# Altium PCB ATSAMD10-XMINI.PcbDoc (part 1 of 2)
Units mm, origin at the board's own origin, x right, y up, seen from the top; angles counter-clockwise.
Board outline 60 x 75 mm, 4 copper layers (Top Layer, GND, Power Plane, Bottom Layer), stack 1.578 mm thick; 62 components, 78 nets, 549 pads, 117 vias.
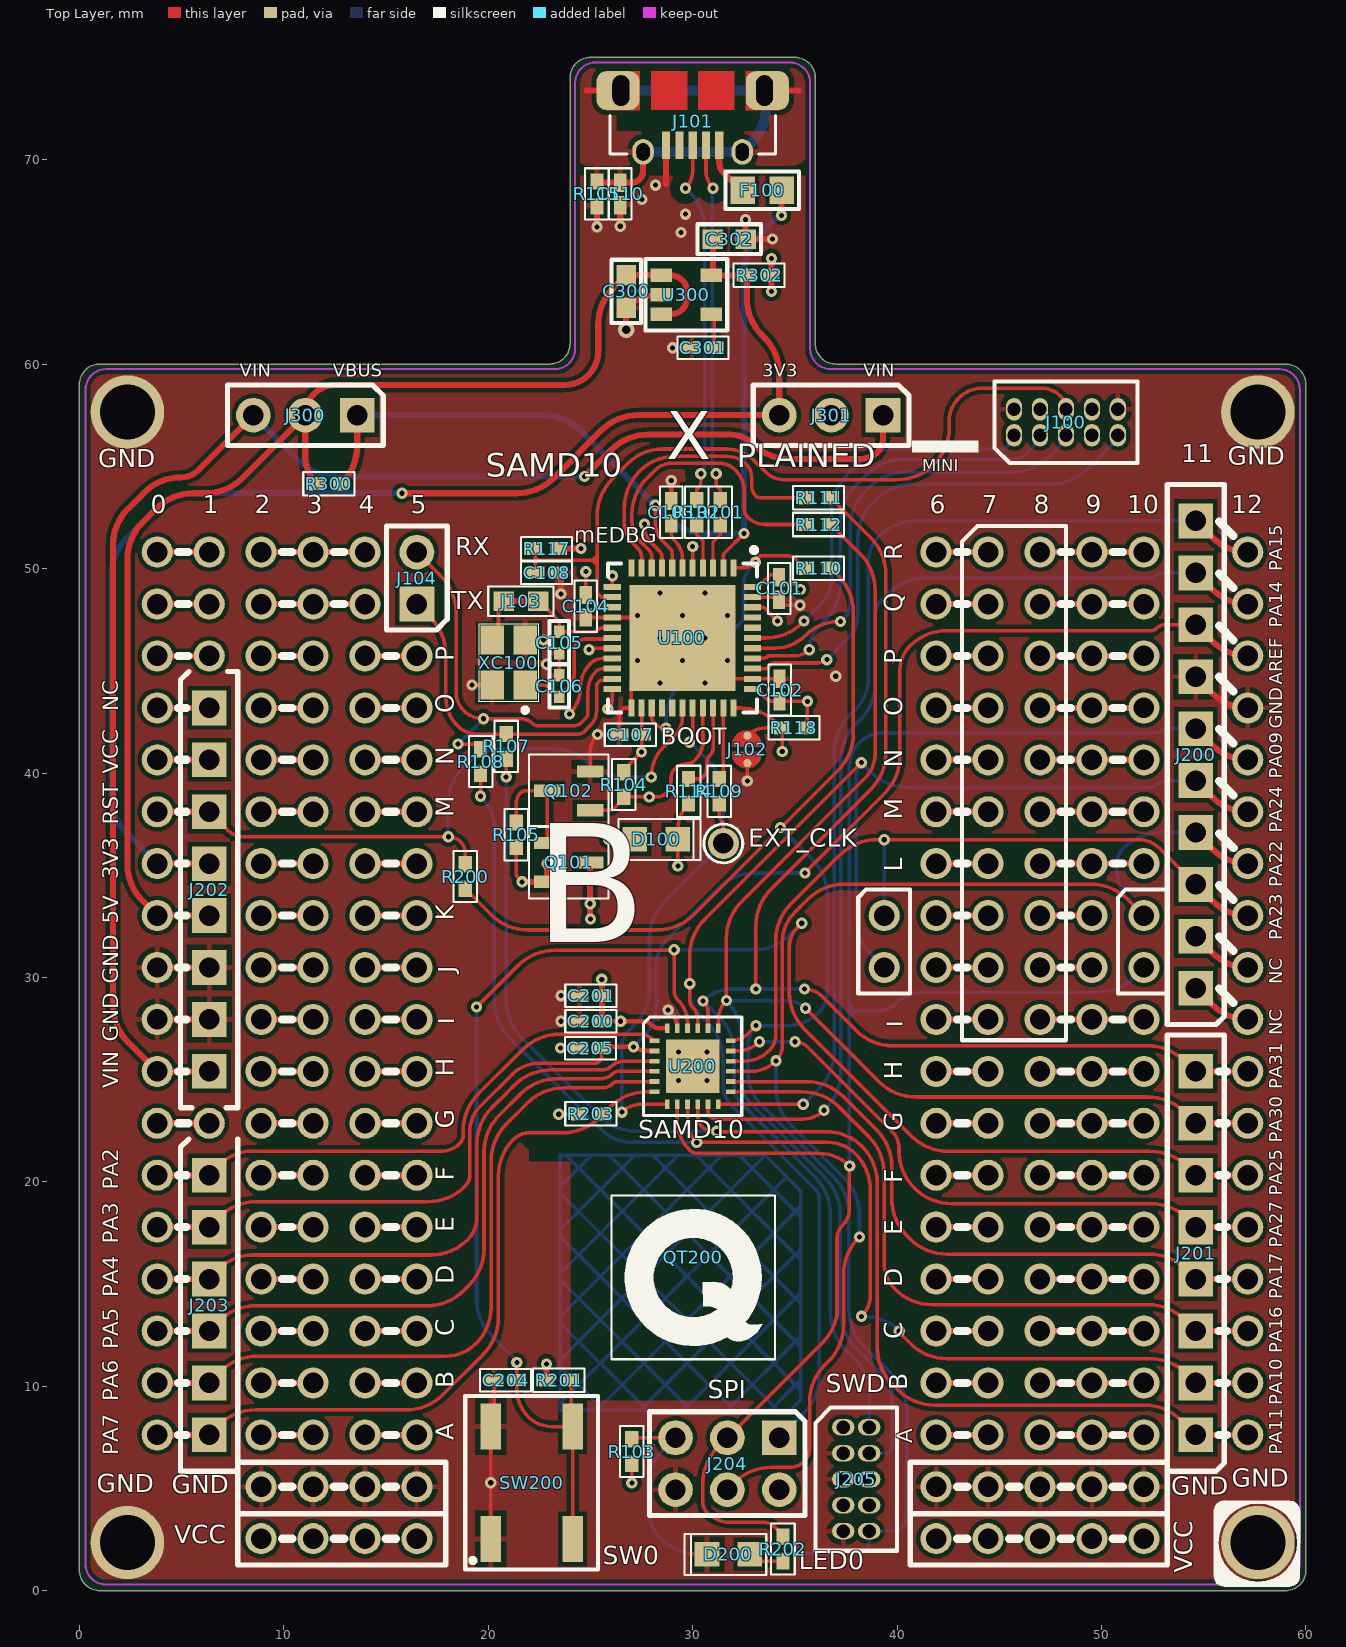
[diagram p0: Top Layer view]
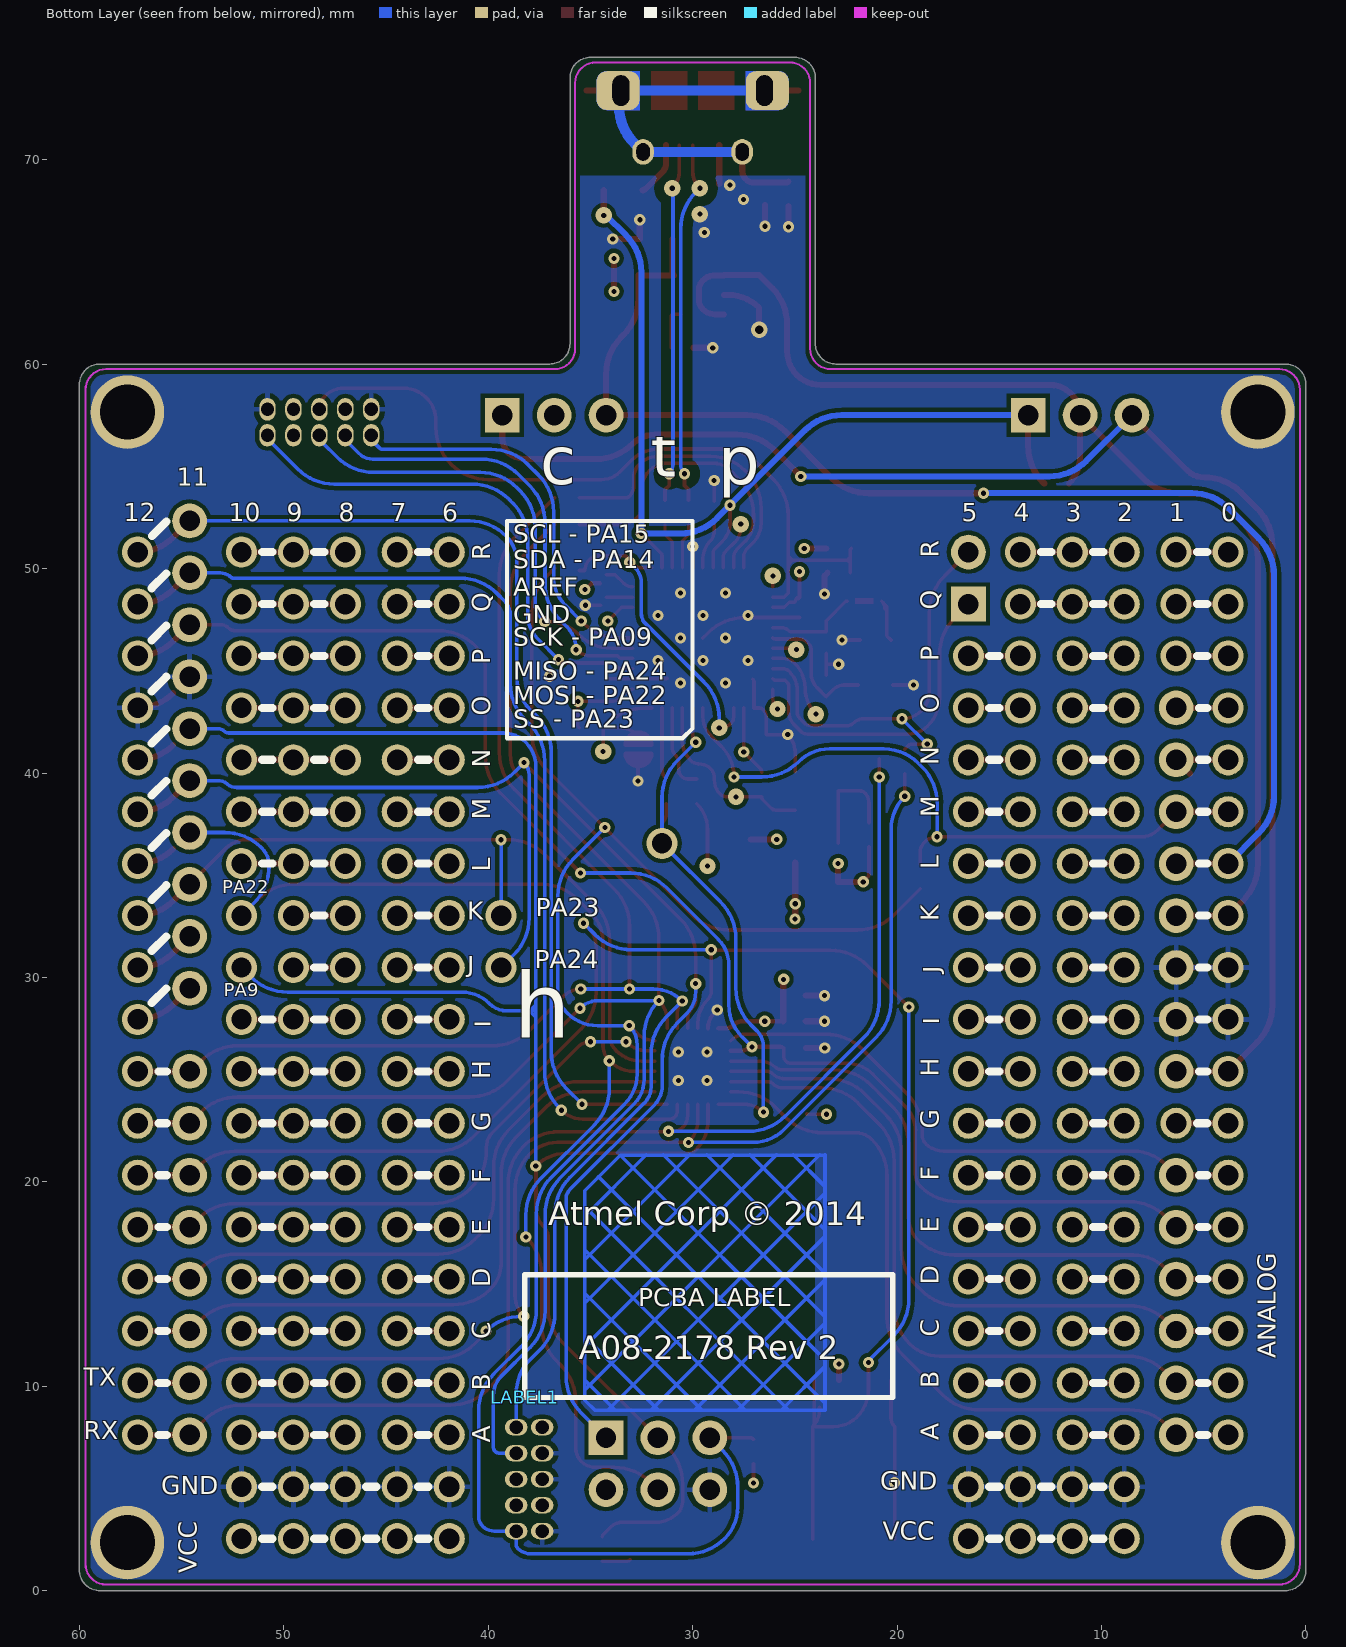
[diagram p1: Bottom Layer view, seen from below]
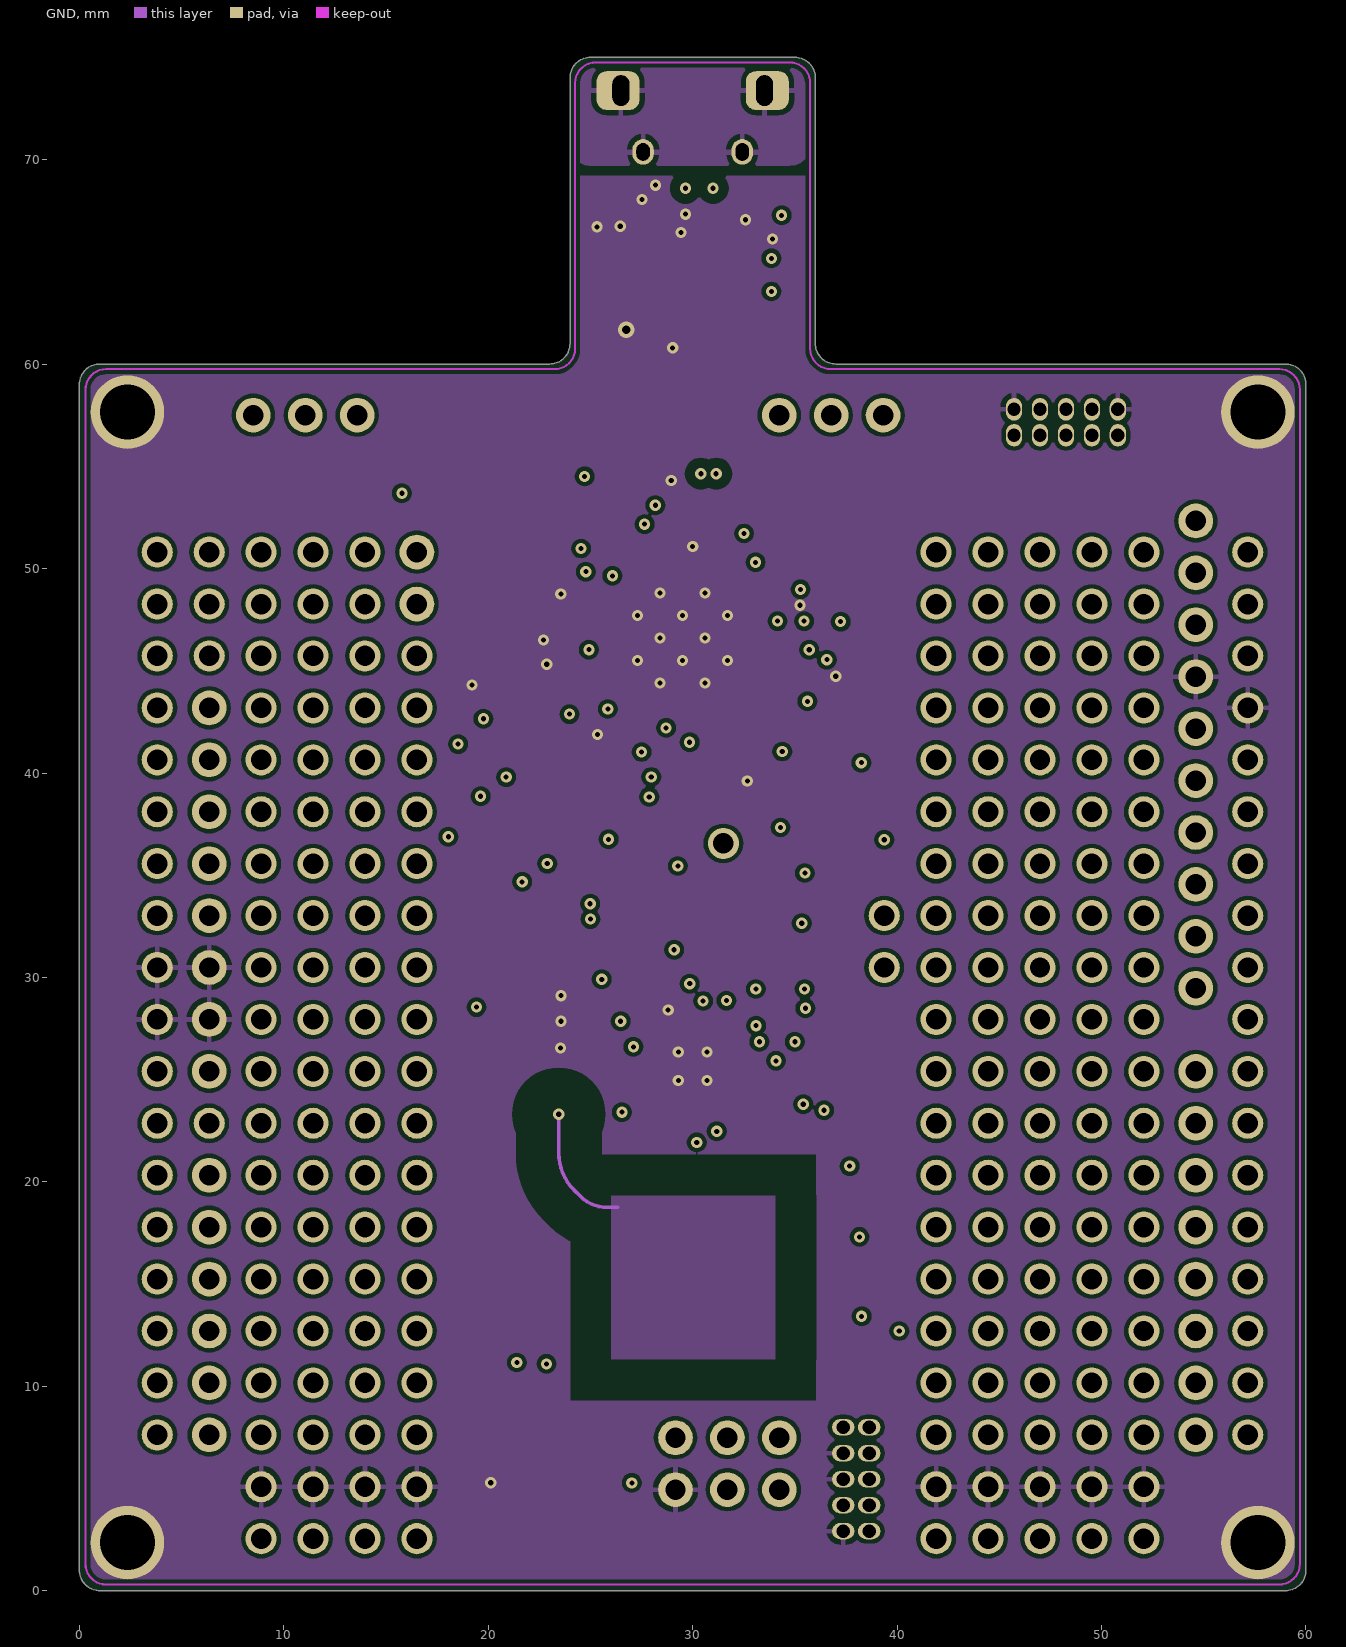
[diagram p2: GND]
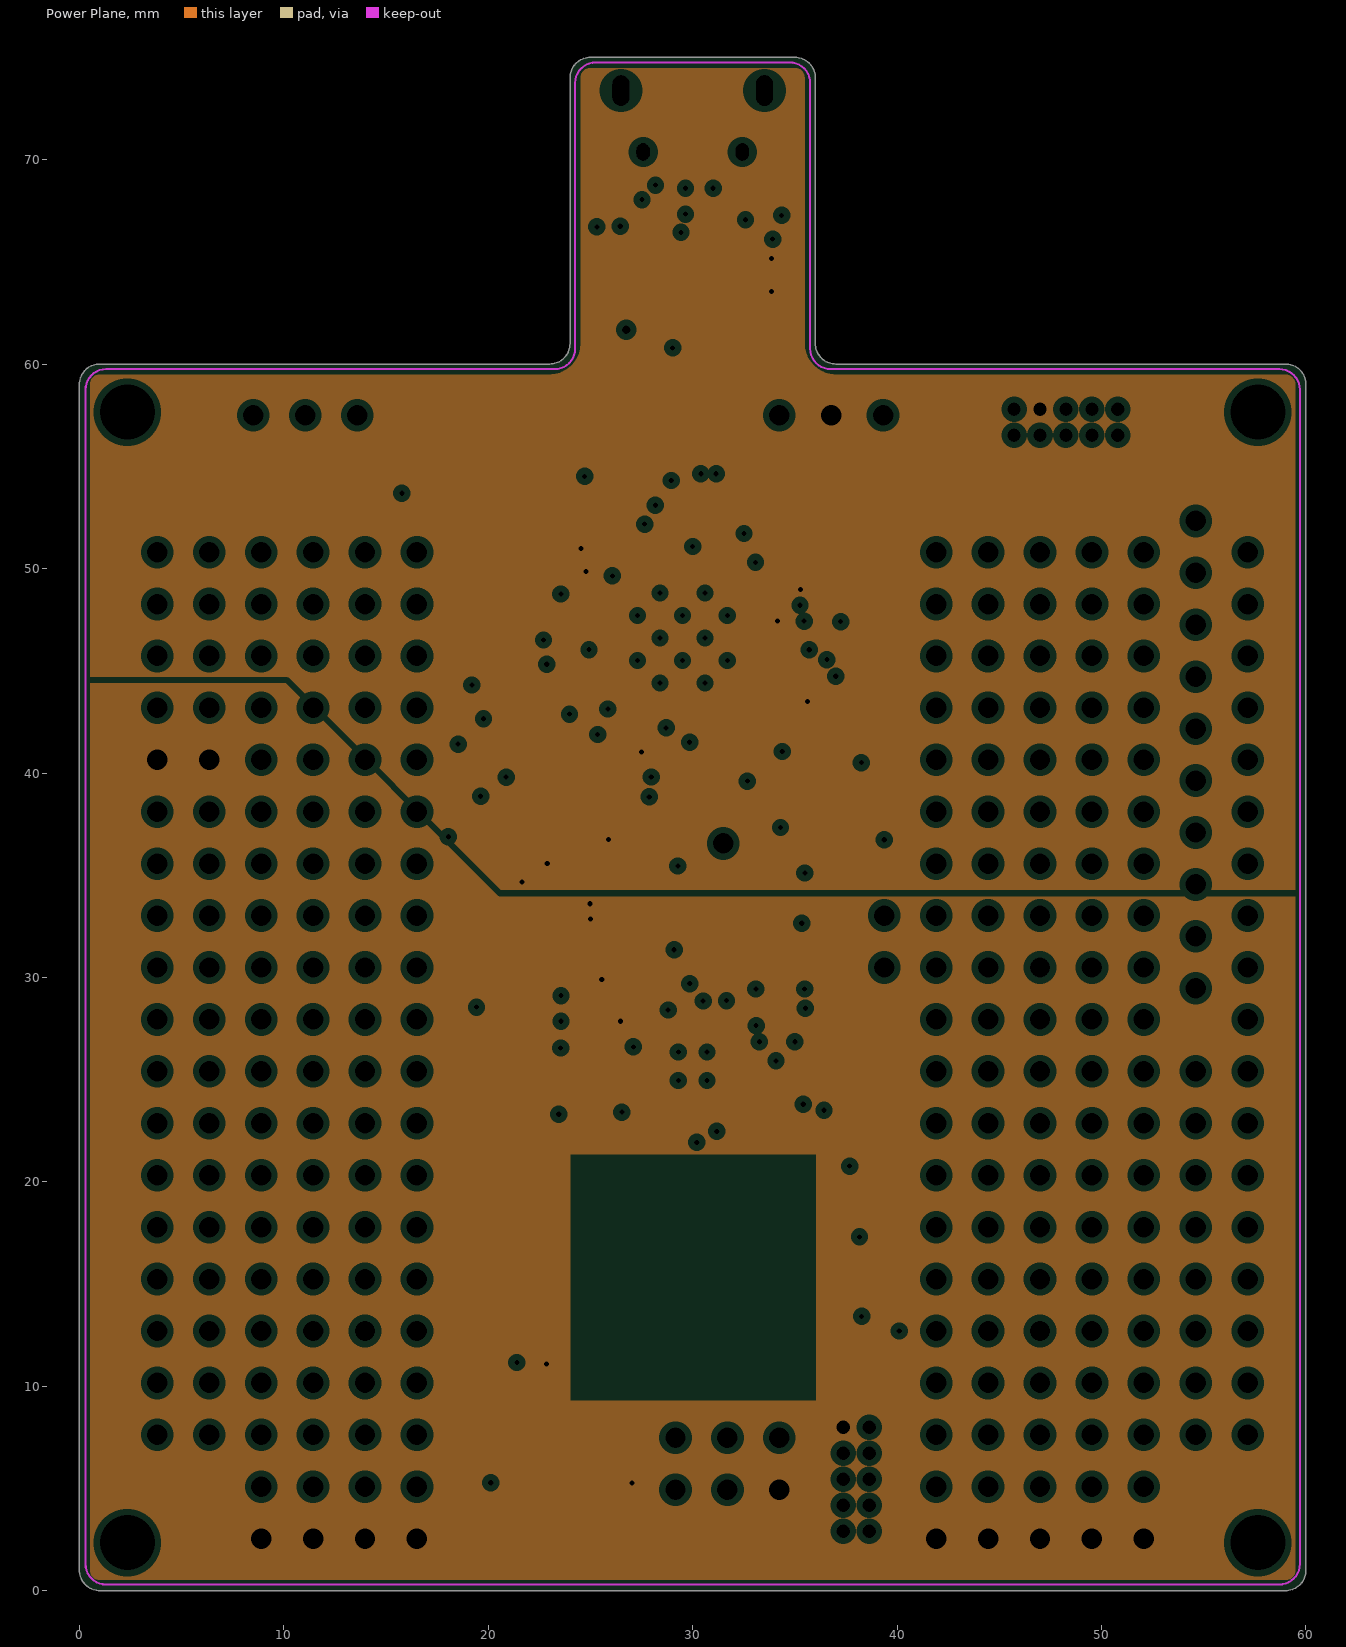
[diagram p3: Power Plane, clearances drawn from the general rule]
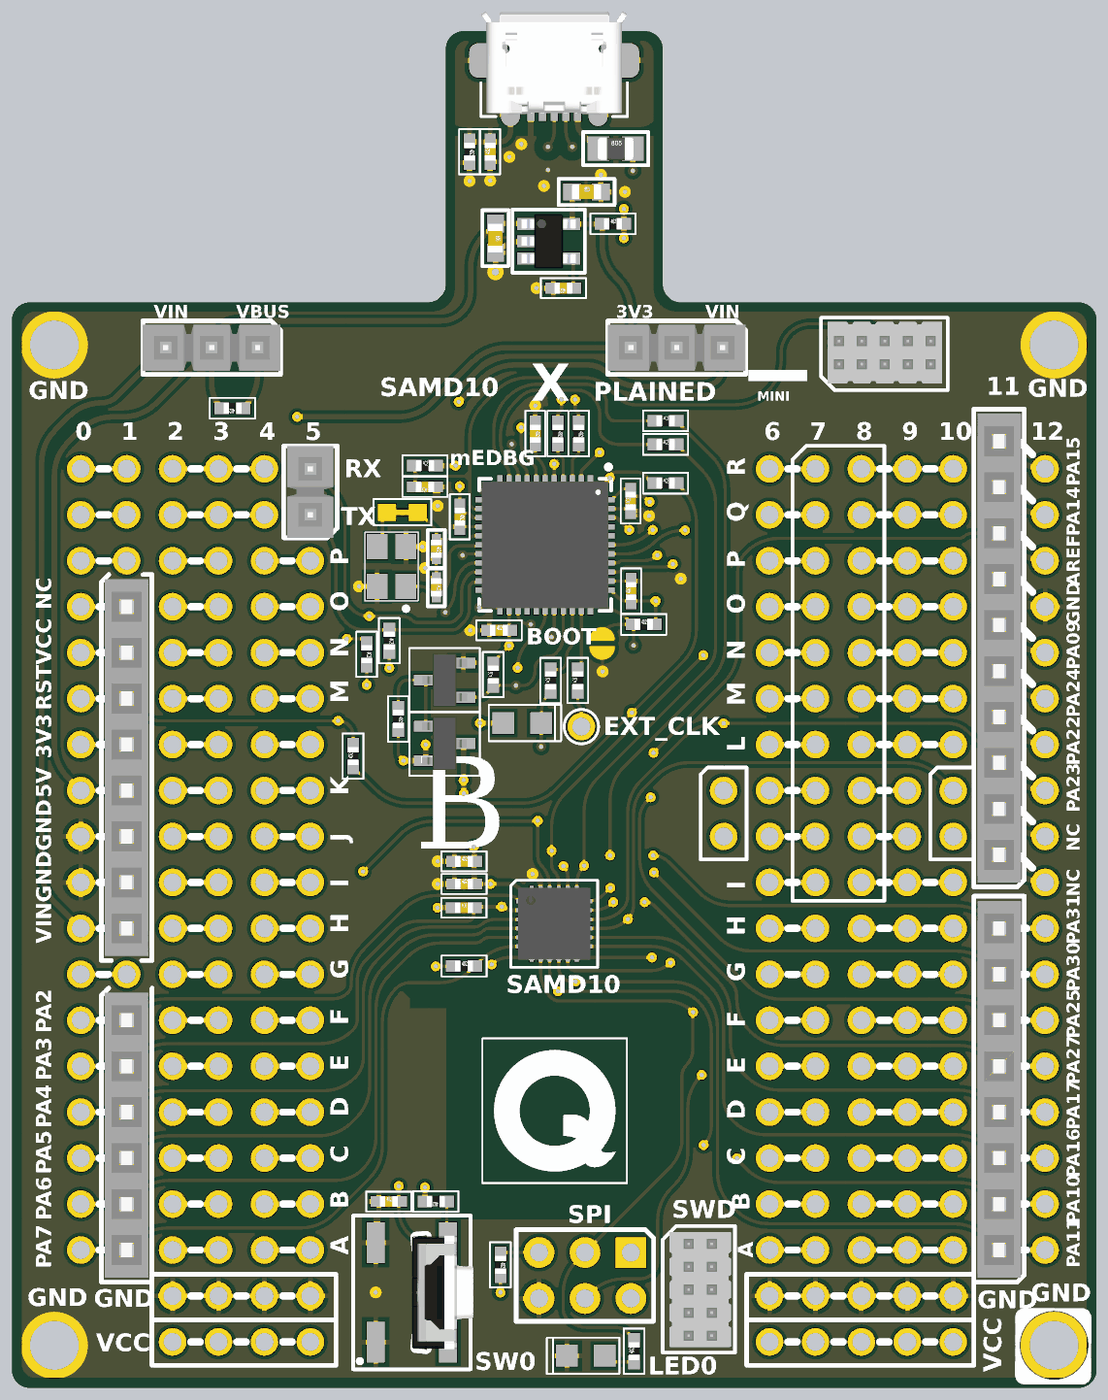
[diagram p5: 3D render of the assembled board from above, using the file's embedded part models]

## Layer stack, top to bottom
Top Solder: solder mask 0.0102, Solder Resist, Dk 3.5
Top Layer: signal copper 0.0356
Dielectric 1: prepreg 0.118, Dk 4.2
GND: signal copper 0.0356
Dielectric 2: core 1.2, Dk 4.2
Power Plane: plane copper 0.0356, net (Multiple Nets)
Dielectric 3: prepreg 0.118, Dk 4.2
Bottom Layer: signal copper 0.0356
Bottom Solder: solder mask 0.0102, Solder Resist, Dk 3.5

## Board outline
0,1.009 0,59.009 cw(c1,59.009) 1,60.009 23,60.009 ccw(c23,61.009) 24,61.009 24,74.009 cw(c25,74.009) 25,75.009 35,75.009 cw(c35,74.009) 36,74.009 36,61.009 ccw(c37,61.009) 37,60.009 59,60.009 cw(c59,59.009) 60,59.009 60,1.009 cw(c59,1.009) 59,0.009 1,0.009 cw(c1,1.009)

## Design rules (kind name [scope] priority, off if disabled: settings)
AcuteAngle [All] p1: minimum=7.50000000000000E+0001 checktracksonly=FALSE
AssemblyTestPointUsage [All] p1: allowmultiple=TRUE
AssemblyTestpoint [All] p1: testpointundercomponent=TRUE minsize=0.55 maxsize=2 preferedsize=0.8 minholesize=0 maxholesize=1 preferedholesize=0.25 testpointgrid=0.025 usegrid=FALSE gridtolerance=0 allowsidebottom=TRUE minspacing=1.27 compbodyclearance=0.127
Clearance Clearance_1 [InNet('NetQT200_1') vs (InNamedPolygon('L2-GND') OR InNamedPolygon('Top-GND'))] p1: gap=2 ignorepadtopadclearanceinfootprint=FALSE except(0: Arc-Hole Track-Hole SMDPad-Hole THPad-Hole Via-Hole Fill-Hole Poly-Hole Region-Hole Text-Hole)
Clearance Clearance_Poly [InPoly vs InNet('USBD_P') OR InNet('USBD_N')] p2: gap=0.5 ignorepadtopadclearanceinfootprint=FALSE except(0: Arc-Hole Track-Hole SMDPad-Hole THPad-Hole Via-Hole Fill-Hole Poly-Hole Region-Hole Text-Hole)
Clearance Clearance_Poly_1 [InPoly] p3: gap=0.2 ignorepadtopadclearanceinfootprint=FALSE except(0: Arc-Hole Track-Hole SMDPad-Hole THPad-Hole Via-Hole Fill-Hole Poly-Hole Region-Hole Text-Hole)
Clearance [All] p4: gap=0.15 ignorepadtopadclearanceinfootprint=FALSE except(0: Arc-Hole Track-Hole SMDPad-Hole THPad-Hole Via-Hole Fill-Hole Poly-Hole Region-Hole Text-Hole)
DiffPairsRouting [All] p1: maxlimit=0.3 minlimit=0.15 mostfreqgap=0.2 toplayer_minwidth=0.15 toplayer_maxwidth=0.18 toplayer_prefwidth=0.15 midlayer1_minwidth=0.15 midlayer1_maxwidth=0.18 midlayer1_prefwidth=0.15 bottomlayer_minwidth=0.15 bottomlayer_maxwidth=0.18 bottomlayer_prefwidth=0.15 maxuncoupledlength=20
FabricationTestPointUsage TestPointUsage [All] p1: valid=0 allowmultiple=TRUE
FabricationTestpoint Testpoint [All] p1: side=2 testpointundercomponent=TRUE minsize=0.55 maxsize=2 preferedsize=0.8 minholesize=0 maxholesize=1 preferedholesize=0.25 testpointgrid=0 allowsidebottom=TRUE usegrid=FALSE gridtolerance=0 minspacing=1.27 compbodyclearance=0.127
HoleSize [All] p1: absolutevalues=TRUE maxlimit=10 minlimit=0.25 maxpercent=80.000 minpercent=20.000
HoleToHoleClearance [All] p1: gap=0.45 allowstackedmicrovias=TRUE
MinimumAnnularRing MinimumAnnularRing_JTAG [(InComponent('J100') AND InComponent('J205'))] p1: minimumring=0.05
MinimumAnnularRing [All] p2: minimumring=0.15
MinimumSolderMaskSliver [All] p1: minsoldermaskwidth=0.05
PlaneClearance [All] p1: clearance=0.3
PlaneConnect PlaneConnect_VIA [IsVia OR HasPad('Free-666')] p1: planeconnectstyle=Direct reliefexpansion=0.508 reliefentries=4 reliefconductorwidth=0.254 reliefairgap=0.254
PlaneConnect [All] p2: planeconnectstyle=Relief reliefexpansion=0.508 reliefentries=4 reliefconductorwidth=0.254 reliefairgap=0.254
PolygonConnect PolygonConnect_VIA [IsVia OR HasPad('Free-666')] p1: connectstyle=Direct reliefconductorwidth=0.254 reliefentries=4 polygonreliefangle="90 Angle" airgapwidth=0.254
PolygonConnect [All] p2: connectstyle=Relief reliefconductorwidth=0.254 reliefentries=4 polygonreliefangle="90 Angle" airgapwidth=0.254
RoutingVias [All] p1: holewidth=0.25 width=0.55 viastyle="Through Hole" minholewidth=0.25 minwidth=0.55 maxholewidth=0.5 maxwidth=1
SMDNeckDown [All] p1: percent=90.000
SilkToSilkClearance SilkToSilkClearance_Text [IsText] p1: silktosilkclearance=0
SilkToSilkClearance [All] p2: silktosilkclearance=0.1
SilkToSolderMaskClearance SilkscreenOverComponentPads [IsPad] p1: minsilkscreentomaskgap=0.05 clearancetoexposedcopper=TRUE
SolderMaskExpansion SolderMaskTenting [IsVia AND NOT (IsFabTestpoint OR IsAssyTestpoint)] p1: expansion=-1
SolderMaskExpansion [All] p2: expansion=0.05
ViasUnderSMD [All] p1: allowed=FALSE
Width [All] p1: maxlimit=10 minlimit=0.175 preferedwidth=0.175
18 further rules are at their usual default settings.

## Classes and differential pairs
component class ATSAMD10-XMINI_TopLevel: FW1 LABEL1 PCB1 PCBADOC1 TEST2 TESTDOC1
component class "Target device": C200 C201 C204 C205 D200 J200 J201 J202 J203 J204 J205 QT200 R200 R201 R202 R203 R204 SW200 U200
component class Programmer/Debug: C101 C102 C103 C104 C105 C106 C107 C108 C110 C300 C301 C302 D100 F100 J100 J101 J102 J103 J104 J300 J301 Q101 Q102 R101 R102 R103 R104 R105 R107 R108 R109 R110 R111 R112 R114 R115 R117 R118 R300 R302 U100 U300 XC100
differential pair D: +D_P -D_N
differential pair USBD: +USBD_P -USBD_N

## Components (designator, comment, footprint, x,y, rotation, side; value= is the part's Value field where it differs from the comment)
C101 "" AP1-00001 34.225,49.034 r90 top value=100n
C102 "" AP1-00001 34.25,44.059 r90 top value=100n
C103 "" AP1-00001 28.95,52.759 r270 top value=1u
C104 "" AP1-00001 24.775,48.159 r270 top value=100n
C105 "" AP1-00038 23.475,45.859 r180 top value=12pF
C106 "" AP1-00038 23.475,43.734 r180 top value=12pF
C107 "" AP1-00001 26.95,41.884 r0 top value=100n
C108 "" AP1-00001 22.85,49.809 r180 top value=100n
C110 "" AP1-00001 26.458,68.335 r90 top value=4.7n
C200 "" AP1-00001 25.016,27.861 r0 top value=100n
C201 "" AP1-00001 25.016,29.111 r0 top value=100n
C204 "" AP1-00001 20.85,10.309 r0 top value=100n
C205 "" AP1-00001 25,26.55 r0 top value=100n
C300 "Farnell no.: 1833806" AP1-00002 26.747,63.561 r270 top value=4.7uF
C301 "" AP1-00001 30.503,60.802 r180 top value=10n
C302 "Farnell no.: 1833806" AP1-00002 31.786,66.12 r0 top value=4.7uF
D100 "" AP4-00013 28.225,36.759 r180 top value=EL17-21SYGC
D200 "" AP4-00013 31.75,1.784 r0 top value=EL17-21UYC/A3
F100 "Farnell no: 1861197" AP2-00002 33.4,68.509 r0 top value=MC36213
J100 "" AP8-00257 48.26,57.159 r0 top locked value="PIN HEADER 2x5"
J101 "2,000 pieces per reel" AP8-00851 30,73.384 r180 top locked value=ZX62D-B-5PA8
J102 "" AP9-00034 32.675,41.159 r90 top net-tie value=SMD-STRAP_OPEN
J103 "" AP9-00044 21.6,48.409 r0 top net-tie value=SMD-STRAP_0603_CLOSED
J104 "" AP8-00733 16.51,49.539 r90 top locked value=HMTSW-102-23-F-S-237
J200 "" AP8-00822 54.61,40.903 r90 top locked value=SSQ-110-21-F-S
J201 "" AP8-00823 54.61,16.519 r90 top locked value=SSQ-108-21-F-S
J202 "" AP8-00823 6.35,34.299 r270 top locked value=SSQ-108-21-F-S
J203 "" AP8-00824 6.35,13.979 r270 top locked value=SSQ-106-21-F-S
J204 "" AP8-00182 31.7,6.219 r180 top locked value=MTSW-103-08-L-D-276
J205 "" AP8-00257 38,5.459 r270 top value="PIN HEADER 2x5"
J300 "" AP8-00745 11.05,57.509 r180 top value=HMTSW-103-23-F-S-237
J301 "" AP8-00745 36.775,57.509 r180 top value=HMTSW-103-23-F-S-237
LABEL1 "" AP8-00317 38.21,9.459 r180 bottom value="Label PCBA"
Q101 "" AP5-00002 23.935,35.629 r0 top value=IRLML6402
Q102 "" AP5-00002 23.935,39.129 r180 top value=2N7002,215
QT200 "QTouch Button" ? 30.028,16.325 r0 top
R101 "" AP2-00000 31.35,52.759 r270 top value=22R
R102 "" AP2-00000 30.2,52.759 r270 top value=22R
R103 "" AP2-00000 27.025,6.809 r270 top value=3.3k
R104 "" AP2-00000 26.625,39.434 r90 top value=100k
R105 "" AP2-00000 21.375,36.984 r270 top value=100k
R107 "" AP2-00000 20.875,41.309 r270 top value=1k
R108 "" AP2-00000 19.625,40.559 r270 top value=1k
R109 "" AP2-00000 31.3,39.109 r90 top value=330R
R110 "" AP2-00000 36.158,50.016 r0 top value=0R
R111 "" AP2-00000 36.158,53.466 r0 top value=330R
R112 "" AP2-00000 36.158,52.159 r0 top value=330R
R114 "" AP2-00000 29.8,39.109 r90 top value=680R
R115 "" AP2-00000 25.315,68.335 r270 top value=1M
R117 "" AP2-00000 22.85,50.984 r0 top value=100k
R118 "" AP2-00000 34.95,42.209 r0 top value=100k
R200 "" AP2-00000 18.875,34.934 r90 top value=0R
R201 "" AP2-00000 23.45,10.309 r180 top value=100k
R202 "" AP2-00000 34.417,2.041 r90 top value=1k
R203 "" AP2-00000 25.016,23.325 r0 top value=100k
R300 "" AP2-00000 12.2,54.159 r180 top value=0R
R302 "" AP2-00000 33.251,64.357 r0 top value=0R
SW200 "" AP8-00137 22.125,5.284 r90 top value=SKRAAKE010
U100 "" AP6-00375 29.5,46.609 r270 top value=ATmega32U4-MUR
U200 "" AP6-00371 30,25.659 r0 top value=ATSAMD10D14A-MUT
U300 "" AP6-00087 29.693,63.392 r0 top value=LP2985-33DBV
XC100 "" AP7-00061 21,45.409 r90 top value=16.0MHz

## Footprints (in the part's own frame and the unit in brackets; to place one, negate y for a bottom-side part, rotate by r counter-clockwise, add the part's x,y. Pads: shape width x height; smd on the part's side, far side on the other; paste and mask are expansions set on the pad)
AP1-00001 [mm] "Standard 0402 SMD capacitor footprint"
  rect 0.9x0.6 smd: 1(-0.55,0) 2(0.55,0)
  silkscreen extent -1.25,-0.55 1.25,0.55, body extent -0.5,-0.3 0.5,0.3, height 0.2
AP1-00002 [mm]
  rect 1x0.95 smd: 1(-0.8,0) 2(0.8,0)
  silkscreen extent -1.55,-0.72 1.55,0.72, body extent -0.8,-0.4 0.8,0.4, height 0.3
AP1-00038 [mm] "Generic pad 0402, spacing 0.45mm"
  rect 0.5x0.6 smd: 1(0,0) 2(0,-1.05)
  silkscreen extent -0.48,-1.58 0.48,0.53, body extent -0.3,-1.02 0.3,-0.03, height 0.2
AP2-00000 [mm] "Standard 0402 SMD resistor footprint"
  rect 0.8x0.65 smd: 1(-0.6,0) 2(0.6,0)
  silkscreen extent -1.25,-0.58 1.25,0.58, body extent -0.5,-0.3 0.5,0.3, height 0.2
AP2-00002 [mm]
  rect 1.2x1.35 smd: 1(-0.95,0) 2(0.95,0)
  silkscreen extent -1.8,-0.92 1.8,0.92, body extent -1,-0.62 1,0.63, height 0.78
AP4-00013 [mm] "0805 diode footprint"
  rect 1.2x1.2 smd: 1(-1.05,0) 2(1.05,0)
  silkscreen extent -2.16,-1 1.85,1, body extent -1,-0.63 1,0.63, height 1.1
AP5-00002 [mm] "SOT-23 Package"
  rect 1.3x0.6 smd: 1(-1.05,0.95) 2(-1.05,-0.95) 3(1.05,0)
  silkscreen extent -1.95,-1.78 1.95,1.78, body extent -1.25,-1.46 1.23,1.46, height 1
AP6-00087 [mm]
  rect 1.05x0.65 smd: 1(-1.225,0.953) 2(-1.225,0) 3(-1.225,-0.953) 4(1.225,-0.953) 5(1.225,0.953)
  silkscreen extent -2,-1.75 2,1.75, body extent -1.5,-1.5 1.5,1.5, height 1.3
AP6-00371 [mm] "QFN24, 4x4mm, 0.4 pitch"
  round 0.6 on Top Paste: 0(-0.65,-0.65) 0(-0.65,0.65) 0(0,0) 0(0.65,-0.65) 0(0.65,0.65)
  rect 0.48x0.23 smd: 1(-1.86,1.25) 2(-1.86,0.75) 3(-1.86,0.25) 4(-1.86,-0.25) 5(-1.86,-0.75) 6(-1.86,-1.25) 13(1.86,-1.25) 14(1.86,-0.75) 15(1.86,-0.25) 16(1.86,0.25) 17(1.86,0.75) 18(1.86,1.25)
  rect 0.23x0.48 smd: 7(-1.25,-1.86) 8(-0.75,-1.86) 9(-0.25,-1.86) 10(0.25,-1.86) 11(0.75,-1.86) 12(1.25,-1.86) 19(1.25,1.86) 20(0.75,1.86) 21(0.25,1.86) 22(-0.25,1.86) 23(-0.75,1.86) 24(-1.25,1.86)
  rect 2.6x2.6 smd paste-2: 25(0,0)
  silkscreen extent -2.4,-2.4 2.4,2.4, body extent -2,-2 2,2, height 1
AP6-00375 [mm] "QFN, 44-Leads, Body 7,00x7,00mm, Pitch 0,50mm, Thermal Pad 5,20x5,20mm, IPC Medium Density"
  rect 0.85x0.3 smd: 1(-3.425,2.5) 2(-3.425,2) 3(-3.425,1.5) 4(-3.425,1) 5(-3.425,0.5) 6(-3.425,0) 7(-3.425,-0.5) 8(-3.425,-1) 9(-3.425,-1.5) 10(-3.425,-2) 11(-3.425,-2.5) 23(3.425,-2.5) 24(3.425,-2) 25(3.425,-1.5) 26(3.425,-1) 27(3.425,-0.5) 28(3.425,0) 29(3.425,0.5) 30(3.425,1) 31(3.425,1.5) 32(3.425,2) 33(3.425,2.5)
  rect 0.3x0.85 smd: 12(-2.5,-3.425) 13(-2,-3.425) 14(-1.5,-3.425) 15(-1,-3.425) 16(-0.5,-3.425) 17(0,-3.425) 18(0.5,-3.425) 19(1,-3.425) 20(1.5,-3.425) 21(2,-3.425) 22(2.5,-3.425) 34(2.5,3.425) 35(2,3.425) 36(1.5,3.425) 37(1,3.425) 38(0.5,3.425) 39(0,3.425) 40(-0.5,3.425) 41(-1,3.425) 42(-1.5,3.425) 43(-2,3.425) 44(-2.5,3.425)
  rect 5.2x5.2 smd: 45(0,0)
  silkscreen extent -4.42,-3.65 3.65,3.65, body extent -3.5,-3.5 3.5,3.5, height 0.89
AP7-00061 [mm] "TSX-3225"
  rect 1.4x1.15 smd: 1(-1.1,-0.8) 2(1.1,-0.8) 3(1.1,0.8) 4(-1.1,0.8)
  silkscreen extent -2.43,-1.48 1.9,1.48, body extent -1.6,-1.25 1.6,1.25, height 0.6
AP8-00137 [mm]
  rect 2.25x1 smd: 1(-2.75,2) 2(2.75,2) 3(-2.75,-2) 4(2.75,-2)
  silkscreen extent -4.25,-3.25 4.25,3.25, body extent -3.4,-3.21 3.4,3.22, height 3.47
AP8-00182 [mm] "Pin-in-Paste, Throughhole pin-header (2x3 array). Pitch 2.54 mm"
  rect 1.7x1.7 / inner round 1.7 / far side rect 1.7x1.7 hole 1: 1(-2.54,-1.27)
  rect 0x0 on Top Paste paste-2: 1(-2.54,-1.27) 2(-2.54,1.27) 3(0,-1.27) 4(0,1.27) 5(2.54,-1.27) 6(2.54,1.27)
  round 1.7 hole 1: 2(-2.54,1.27) 3(0,-1.27) 4(0,1.27) 5(2.54,-1.27) 6(2.54,1.27)
  silkscreen extent -3.8,-2.54 3.81,2.54, body extent -3.81,-2.54 3.81,2.54, height 8
AP8-00257 [mm]
  oval 0.8x1.1 hole 0.65: 1(-2.54,-0.635) 2(-2.54,0.635) 3(-1.27,-0.635) 4(-1.27,0.635) 5(0,-0.635) 6(0,0.635) 7(1.27,-0.635) 8(1.27,0.635) 9(2.54,-0.635) 10(2.54,0.635)
  oval 0.75x1.1 on Top Paste: 1(-2.54,-0.635) 2(-2.54,0.635) 3(-1.27,-0.635) 4(-1.27,0.635) 5(0,-0.635) 6(0,0.635) 7(1.27,-0.635) 8(1.27,0.635) 9(2.54,-0.635) 10(2.54,0.635)
  silkscreen extent -3.5,-2 3.5,2, body extent -3.15,-1.64 3.2,1.79, height 3.88
AP8-00317 [mm] "Placement area for 18x6mm sticker"
  silkscreen extent 0,0 18,6
AP8-00733 [mm] "Pin header 1x2 Pin in Paste"
  rect 1.7x1.7 / inner round 1.7 / far side rect 1.7x1.7 hole 1: 1(-1.27,0)
  rect 0x0 on Top Paste paste-2: 1(-1.27,0)
  round 1.7 hole 1: 2(1.27,0)
  rect 0x0 on Top Paste paste+2: 2(1.27,0)
  silkscreen extent -2.54,-1.48 2.54,1.48, body extent -2.54,-1.27 2.54,1.27, height 8.38
AP8-00745 [mm] "THM Pin-header 1x3 100mil pitch, 1mm hole"
  rect 1.7x1.7 / inner round 1.7 / far side rect 1.7x1.7 hole 1: 1(-2.54,0)
  rect 2.1x2.1 on Top Paste: 1(-2.54,0) 2(0,0) 3(2.54,0)
  round 1.7 hole 1: 2(0,0) 3(2.54,0)
  silkscreen extent -3.81,-1.48 3.81,1.48, body extent -3.81,-1.27 3.81,1.27, height 8.38
AP8-00822 [mm]
  rect 1.7x1.7 / inner round 1.7 / far side round 1.7 hole 1: 1(-11.43,0) 2(-8.89,0) 3(-6.35,0) 4(-3.81,0) 5(-1.27,0) 6(1.27,0) 7(3.81,0) 8(6.35,0) 9(8.89,0)
  rect 0x0 on Top Paste paste-2: 1(-11.43,0) 2(-8.89,0) 3(-6.35,0) 4(-3.81,0) 5(-1.27,0) 6(1.27,0) 7(3.81,0) 8(6.35,0) 9(8.89,0)
  rect 1.7x1.7 / inner round 1.7 / far side round 1.7 hole 1 paste+2: 10(11.43,0)
  rect 0x0 on Top Paste paste+2: 10(11.43,0)
  silkscreen extent -13.21,-1.4 13.21,1.4, body extent -12.95,-1.21 12.95,1.21, height 8.51
AP8-00823 [mm]
  rect 1.7x1.7 / inner round 1.7 / far side round 1.7 hole 1: 1(-8.89,0) 2(-6.35,0) 3(-3.81,0) 4(-1.27,0) 5(1.27,0) 6(3.81,0) 7(6.35,0) 8(8.89,0)
  rect 0x0 on Top Paste paste-2: 1(-8.89,0) 2(-6.35,0) 3(-3.81,0) 4(-1.27,0) 5(1.27,0) 6(3.81,0) 7(6.35,0) 8(8.89,0)
  silkscreen extent -10.67,-1.4 10.67,1.4, body extent -10.41,-1.21 10.41,1.21, height 8.51
AP8-00824 [mm]
  rect 1.7x1.7 / inner round 1.7 / far side round 1.7 hole 1: 1(-6.35,0) 2(-3.81,0) 3(-1.27,0) 4(1.27,0) 5(3.81,0) 6(6.35,0)
  rect 0x0 on Top Paste paste-2: 1(-6.35,0) 2(-3.81,0) 3(-1.27,0) 4(1.27,0) 5(3.81,0) 6(6.35,0)
  silkscreen extent -8.13,-1.4 8.13,1.4, body extent -7.87,-1.21 7.87,1.21, height 8.51
AP8-00851 [mm] "Hirose, ZX Series, USB Micro-B Recept-RA"
  rect 0.4x1.35 smd: 1(-1.3,2.675) 2(-0.65,2.675) 3(0,2.675) 4(0.65,2.675) 5(1.3,2.675)
  rrect52% 2.1x1.9 on Top Paste: 6(-3.6,0) 7(3.6,0)
  rrect52% 2.1x1.9 hole 0.825 slot 1.5 at 90 deg copper offset -0.138,0: 6(-3.512,0)
  rrect52% 2.1x1.9 hole 0.825 slot 1.5 at 90 deg copper offset 0.138,0: 7(3.512,0)
  rrect100% 1.05x1.25 hole 0.65 slot 0.85 at 90 deg: 8(-2.425,3) 9(2.425,3)
  rrect100% 1.05x1.25 on Top Paste: 8(-2.425,3) 9(2.425,3)
  Top Layer region: 0.249,-0.95 2.049,-0.95 2.049,0.95 0.249,0.95
  Top Layer region: -2.049,-0.95 -0.249,-0.95 -0.249,0.95 -2.049,0.95
  Top Layer region: 2.6,-0.95 4.2,-0.95 4.294,-0.941 4.381,-0.915 4.434,-0.891 4.48,-0.862 4.52,-0.832 4.565,-0.791 4.596,-0.753 4.622,-0.716 4.647,-0.673 4.66,-0.64 4.676,-0.6 4.688,-0.55 4.696,-0.505 4.7,-0.45 4.7,0.45 4.696,0.503 4.689,0.548 4.677,0.599 4.661,0.641 4.641,0.683 4.617,0.724 4.589,0.761 4.56,0.797 4.521,0.831 4.483,0.86 4.439,0.888 4.397,0.908 4.354,0.924 4.301,0.939 4.248,0.946 4.2,0.95 2.6,0.95
  Top Layer region: -2.6,0.95 -4.2,0.95 -4.294,0.941 -4.381,0.915 -4.434,0.891 -4.48,0.862 -4.52,0.832 -4.565,0.791 -4.596,0.753 -4.622,0.716 -4.647,0.673 -4.66,0.64 -4.676,0.6 -4.688,0.55 -4.696,0.505 -4.7,0.45 -4.7,-0.45 -4.696,-0.503 -4.689,-0.548 -4.677,-0.599 -4.661,-0.641 -4.641,-0.683 -4.617,-0.724 -4.589,-0.761 -4.56,-0.797 -4.521,-0.831 -4.483,-0.86 -4.439,-0.888 -4.397,-0.908 -4.354,-0.924 -4.301,-0.939 -4.248,-0.946 -4.2,-0.95 -2.6,-0.95
  Top Layer pour cut-out: -3.75,2 3.75,2 3.75,-1.45 -3.75,-1.45
  Bottom Layer region: -2.6,0.95 -4.2,0.95 -4.294,0.941 -4.381,0.915 -4.434,0.891 -4.48,0.862 -4.52,0.832 -4.565,0.791 -4.596,0.753 -4.622,0.716 -4.647,0.673 -4.66,0.64 -4.676,0.6 -4.688,0.55 -4.696,0.505 -4.7,0.45 -4.7,-0.45 -4.696,-0.503 -4.689,-0.548 -4.677,-0.599 -4.661,-0.641 -4.641,-0.683 -4.617,-0.724 -4.589,-0.761 -4.56,-0.797 -4.521,-0.831 -4.483,-0.86 -4.439,-0.888 -4.397,-0.908 -4.354,-0.924 -4.301,-0.939 -4.248,-0.946 -4.2,-0.95 -2.6,-0.95
  Bottom Layer region: 2.6,-0.95 4.2,-0.95 4.294,-0.941 4.381,-0.915 4.434,-0.891 4.48,-0.862 4.52,-0.832 4.565,-0.791 4.596,-0.753 4.622,-0.716 4.647,-0.673 4.66,-0.64 4.676,-0.6 4.688,-0.55 4.696,-0.505 4.7,-0.45 4.7,0.45 4.696,0.503 4.689,0.548 4.677,0.599 4.661,0.641 4.641,0.683 4.617,0.724 4.589,0.761 4.56,0.797 4.521,0.831 4.483,0.86 4.439,0.888 4.397,0.908 4.354,0.924 4.301,0.939 4.248,0.946 4.2,0.95 2.6,0.95
  silkscreen extent -4.05,1.22 4.05,3.1, body extent -4.05,-2.7 4.05,3.1, height 2.75
AP9-00034 [mm] "PCB implemented strap, open"
  round 0.4 smd paste-0.4 mask-0.4: 1(-0.675,0) 2(0.675,0)
  Top Layer region: 0.2,0.675 0.482,0.611 0.708,0.43 0.834,0.17 0.834,-0.12 0.708,-0.38 0.482,-0.561 0.2,-0.625 0.2,-0.625
  Top Layer region: -0.2,-0.625 -0.482,-0.561 -0.708,-0.38 -0.834,-0.12 -0.834,0.17 -0.708,0.43 -0.482,0.611 -0.2,0.675 -0.2,0.675
  Top Layer lines w0.175: -0.2,0.675 ccw(c-0.2,0.025) -0.2,-0.625 -0.2,0.675 ; 0.2,0.675 cw(c0.2,0.025) 0.2,-0.625 0.2,0.675
AP9-00044 [mm]
  rect 1x0.95 smd paste-1: 1(-0.85,0) 2(0.85,0)
  Top Layer region: -0.45,-0.15 0.45,-0.15 0.45,0.15 -0.45,0.15
  silkscreen extent -1.6,-0.72 1.6,0.72, body extent -0.8,-0.4 0.8,0.4, height 0.3
? [mm]
  round 0.1 on Plane2 paste-0.05: 1(0,0)

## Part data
C101 C102 C104 C107 C108 C200 C201 C204 C205: library part A01-0246, "Ceramic capacitor, SMD 0402, X7R, 16V, +/-10%", Manufacturer=Kemet, MPN=C0402C104K4RACTU, TemperatureRange="-55 - +125 deg C", Tolerance="16V, +/-10%"
C103: library part A01-0286, "Ceramic capacitor, SMD 0402, X5R, 6.3V, +/-10% (de26942)", Manufacturer=Kemet, MPN=C0402C105K9PAC, TemperatureRange="-55 to 85 deg C", Tolerance=+/-10%
C105 C106: library part A01-0355, "Ceramic capacitor, SMD 0402, NP0, 50V, +/-5% (de19819)", Manufacturer=Kyocera-elco, MPN=CM05CG120J50AH, TemperatureRange="-55 - +125 deg C", Tolerance=5%
C110: library part A01-0046, "Ceramic capacitor, SMD 0402, X7R, 25V, +/-10% (de35287)", Manufacturer=PHYCOMP, MPN="2238 587 15632", TemperatureRange="-55 - +125 deg C", Tolerance="25V, +/-10%"
C300 C302: library part A01-0502, "Ceramic capacitor, SMD 0603, X5R, 10V, ±10 %", Manufacturer=AVX, MPN=0603ZD475KAT2A, TemperatureRange="Â–55 to +85 deg C", Tolerance=±10%
C301: library part A01-0050, "Ceramic capacitor, SMD 0402, X7R, 25V, +/-10%", Manufacturer="YAGEO CORP", MPN=CC0402KRX7R8BB103, TemperatureRange="-55 - +125 deg C", Tolerance="25V, +/-10%"
D100: library part A10-0018, "LED, Green, Wave length=575nm, SMD 0805, ±70°", Manufacturer=Everlight, MPN=EL17-21SYGC, TemperatureRange="-40 - +85 deg C"
D200: library part A10-0019, "LED, Yellow, Wave length=591nm, SMD 0805, ±70°", Manufacturer=Everlight, MPN=17-21UYC/S530-A3/TR8, TemperatureRange="-40 to +85 deg C"
F100: library part A02-0622, "Resetable PTC fuse, Ih = 0.5A, It = 1.0A, 0805 package", Manufacturer=Multicomp, MPN=MC36213, TemperatureRange="-40°C to + 85°C"
J100 J205: library part A08-0385, "2x5 pin header, 1.27mm pitch, THM", Manufacturer=Garry, MPN=176-2-010-0-T-XS0-0730
J101: library part A08-2092, "Micro USB B Connector, Standard SMT + DIP", Manufacturer=HIROSE, MPN=ZX62D-B-5PA8(30)
J102: library part A09-0483, "Default open SMD strap"
J103: library part A09-0783, "Default closed SMD strap, 0603 size"
J104: library part A08-1754, "1x2 pin header, 2.54mm pitch, Pin-in-Paste THM", Manufacturer=SAMTEC, MPN=HMTSW-102-23-F-S-237, TemperatureRange="- 55 deg C to + 125 deg C"
J200: library part A08-2026, "1x10 receptacle pin header, low insertion force, 2.54mm pitch THM, Pin in Paste", Manufacturer=SAMTEC, MPN=SSQ-110-21-F-S
J201 J202: library part A08-2025, "1x8 receptacle pin header, low insertion force, 2.54mm pitch THM, Pin in Paste", Manufacturer=SAMTEC, MPN=SSQ-108-21-F-S
J203: library part A08-2024, "1x6 receptacle pin header, low insertion force, 2.54mm pitch THM", Manufacturer=SAMTEC, MPN=SSQ-106-21-F-S
J204: library part A08-0538, "2x3 pin header, 2.54 mm pitch, THM", Manufacturer=SAMTEC, MPN=MTSW-103-08-L-D-276, TemperatureRange="max. 125 degrees"
J300 J301: library part A08-1799, "1x3 pin header, 2.54mm pitch, Pin-in-Paste THM, 1mm hole", Manufacturer=SAMTEC, MPN=HMTSW-103-23-F-S-237
LABEL1: library part A09-0611, "PCBA identification label PP Top White Gloss", Manufacturer="ACT Logimark AS", MPN=505462
Q101: library part A05-0087, "P-ch. MOSFET. -30V, -3.7A continuous,RDS(ON)=0.05Ohm@VGS=-4,5V, RDS(ON)=0.08Ohm@VGS=-2.5V", Manufacturer="International Rectifier", MPN=IRLML6402PBF, TemperatureRange="-55 - +150 deg C"
Q102: library part A05-0085, "N-Channel MOSFET. 60V, 0.300A continuous, 1.2A Peak. RDS(ON) = 3.8Ohm@VGS=4.5V, VGS(th)<2.5V", Manufacturer=NXP, MPN=2N7002,215, TemperatureRange="-65 to 150 deg C"
QT200: library part QTouchButton
R101 R102: library part A02-0172, "Thick film resistor, SMD 0402, 1/16W, 1% (de23607)", Manufacturer=Samsung, MPN=RC100SF22R0CS, TemperatureRange="-55 - +125 deg C", Tolerance="1 %"
R103: library part A02-0224, "Thick film resistor, SMD 0402, 1/16W, 1%", Manufacturer=ASJ, MPN=CR10-3301-FK, TemperatureRange="-55 - +125 deg C", Tolerance="1 %"
R104 R105 R117 R118 R201 R203: library part A02-0260, "Thick film resistor, SMD 0402, 1/16W, 1%", Manufacturer=ASJ, MPN=CR10-1003-FK, TemperatureRange="-55� to +125�C", Tolerance="1 %"
R107 R108 R202: library part A02-0212, "Thick film resistor, SMD 0402, 1/16W, 1%", Manufacturer=ASJ, MPN=CR10-1001-FK, TemperatureRange="-55 - +125 deg C", Tolerance="1 %"
R109 R111 R112: library part A02-0200, "Thick film resistor, SMD 0402, 1/16W, 1%", Manufacturer=ASJ, MPN=CR10-3300-FK, TemperatureRange="-55 - +125 deg C", Tolerance="1 %"
R110 R200 R300 R302: library part A02-0163, "RES 0.0 OHM 1/16W 0402 SMD", Manufacturer=(n/a), MPN=RMCF0402ZT0R00, TemperatureRange="-55 - +125 deg C", Tolerance="1 %"
R114: library part A02-0208, "Thick film resistor, SMD 0402, 1/16W, 1%", Manufacturer=ASJ, MPN=CR10-6800-FK, TemperatureRange="-55 - +125 deg C", Tolerance="1 %"
R115: library part A02-0284, "Thick film resistor, SMD 0402, 1/16W, 1%", Manufacturer=ASJ, MPN=CR10-1004-FK, TemperatureRange="-55 - +125 deg C", Tolerance="1 %"
SW200: library part A08-0790, "6.2x6.2 mm SMD tact switch, same as A08-0091 but less force is needed", Manufacturer=ALPS, MPN=SKRAAKE010, TemperatureRange="-30 - +90 deg C"
U100: library part A06-0305, "ATmega32U4 QFN package", Manufacturer=ATMEL, MPN=ATmega32U4-MUR
U200: library part A06-1148, "Atmel 32-bit RISC MCU", Manufacturer=ATMEL, MPN=ATSAMD10D14A-MUT
U300: library part A06-1099, "LDO 3.3V 150mA SOT23-5 1.5% (cer. cap)", Manufacturer="Texas Instruments", MPN=LP2985-33DBV, TemperatureRange="-40 - +125 deg. C", Tolerance=1.5%
XC100: library part A07-0078, "16MHz uXtal, 3.2 x 2.5 mm SMD, CL=9pF, 15PPM, ESR=80ohm(Max.", Manufacturer="Epson Toyocom", MPN="TSX-3225 16.0000MF09Z-AC3", TemperatureRange="-40°C to +85°C", Tolerance=15ppm

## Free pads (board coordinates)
  round 1.524 hole 1: 0(3.81,7.629) 0(3.81,10.169) 0(3.81,12.709) 0(3.81,15.249) 0(3.81,17.789) 0(3.81,20.329) 0(3.81,22.869) 0(3.81,25.409) 0(3.81,27.949) 0(3.81,30.489) 0(3.81,33.029) 0(3.81,35.569) 0(3.81,38.109) 0(3.81,40.649) 0(3.81,43.189) 0(3.81,45.729) 0(3.81,48.269) 0(3.81,50.809) 1(6.35,22.869) 1(6.35,45.729) 1(6.35,48.269) 1(6.35,50.809) 2(8.89,2.549) 2(8.89,5.089) 2(8.89,7.629) 2(8.89,10.169) 2(8.89,12.709) 2(8.89,15.249) 2(8.89,17.789) 2(8.89,20.329) 2(8.89,22.869) 2(8.89,25.409) 2(8.89,27.949) 2(8.89,30.489) 2(8.89,33.029) 2(8.89,35.569) 2(8.89,38.109) 2(8.89,40.649) 2(8.89,43.189) 2(8.89,45.729) 2(8.89,48.269) 2(8.89,50.809) 3(11.43,2.549) 3(11.43,5.089) 3(11.43,7.629) 3(11.43,10.169) 3(11.43,12.709) 3(11.43,15.249) 3(11.43,17.789) 3(11.43,20.329) 3(11.43,22.869) 3(11.43,25.409) 3(11.43,27.949) 3(11.43,30.489) 3(11.43,33.029) 3(11.43,35.569) 3(11.43,38.109) 3(11.43,40.649) 3(11.43,43.189) 3(11.43,45.729) 3(11.43,48.269) 3(11.43,50.809) 4(13.97,2.549) 4(13.97,5.089) 4(13.97,7.629) 4(13.97,10.169) 4(13.97,12.709) 4(13.97,15.249) 4(13.97,17.789) 4(13.97,20.329) 4(13.97,22.869) 4(13.97,25.409) 4(13.97,27.949) 4(13.97,30.489) 4(13.97,33.029) 4(13.97,35.569) 4(13.97,38.109) 4(13.97,40.649) 4(13.97,43.189) 4(13.97,45.729) 4(13.97,48.269) 4(13.97,50.809) 5(16.51,2.549) 5(16.51,5.089) 5(16.51,7.629) 5(16.51,10.169) 5(16.51,12.709) 5(16.51,15.249) 5(16.51,17.789) 5(16.51,20.329) 5(16.51,22.869) 5(16.51,25.409) 5(16.51,27.949) 5(16.51,30.489) 5(16.51,33.029) 5(16.51,35.569) 5(16.51,38.109) 5(16.51,40.649) 5(16.51,43.189) 5(16.51,45.729) 6(31.5,36.559) 6(41.91,2.549) 6(41.91,5.089) 6(41.91,7.629) 6(41.91,10.169) 6(41.91,12.709) 6(41.91,15.249) 6(41.91,17.789) 6(41.91,20.329) 6(41.91,22.869) 6(41.91,25.409) 6(41.91,27.949) 6(41.91,30.489) 6(41.91,33.029) 6(41.91,35.569) 6(41.91,38.109) 6(41.91,40.649) 6(41.91,43.189) 6(41.91,45.729) 6(41.91,48.269) 6(41.91,50.809) 7(44.45,2.549) 7(44.45,5.089) 7(44.45,7.629) 7(44.45,10.169) 7(44.45,12.709) 7(44.45,15.249) 7(44.45,17.789) 7(44.45,20.329) 7(44.45,22.869) 7(44.45,25.409) 7(44.45,27.949) 7(44.45,30.489) 7(44.45,33.029) 7(44.45,35.569) 7(44.45,38.109) 7(44.45,40.649) 7(44.45,43.189) 7(44.45,45.729) 7(44.45,48.269) 7(44.45,50.809) 8(46.99,2.549) 8(46.99,5.089) 8(46.99,7.629) 8(46.99,10.169) 8(46.99,12.709) 8(46.99,15.249) 8(46.99,17.789) 8(46.99,20.329) 8(46.99,22.869) 8(46.99,25.409) 8(46.99,27.949) 8(46.99,30.489) 8(46.99,33.029) 8(46.99,35.569) 8(46.99,38.109) 8(46.99,40.649) 8(46.99,43.189) 8(46.99,45.729) 8(46.99,48.269) 8(46.99,50.809) 9(49.53,2.549) 9(49.53,5.089) 9(49.53,7.629) 9(49.53,10.169) 9(49.53,12.709) 9(49.53,15.249) 9(49.53,17.789) 9(49.53,20.329) 9(49.53,22.869) 9(49.53,25.409) 9(49.53,27.949) 9(49.53,30.489) 9(49.53,33.029) 9(49.53,35.569) 9(49.53,38.109) 9(49.53,40.649) 9(49.53,43.189) 9(49.53,45.729) 9(49.53,48.269) 9(49.53,50.809) 10(52.07,2.549) 10(52.07,5.089) 10(52.07,7.629) 10(52.07,10.169) 10(52.07,12.709) 10(52.07,15.249) 10(52.07,17.789) 10(52.07,20.329) 10(52.07,22.869) 10(52.07,25.409) 10(52.07,27.949) 10(52.07,30.489) 10(52.07,33.029) 10(52.07,35.569) 10(52.07,38.109) 10(52.07,40.649) 10(52.07,43.189) 10(52.07,45.729) 10(52.07,48.269) 10(52.07,50.809) 12(57.15,7.629) 12(57.15,10.169) 12(57.15,12.709) 12(57.15,15.249) 12(57.15,17.789) 12(57.15,20.329) 12(57.15,22.869) 12(57.15,25.409) 12(57.15,27.949) 12(57.15,30.489) 12(57.15,33.029) 12(57.15,35.569) 12(57.15,38.109) 12(57.15,40.649) 12(57.15,43.189) 12(57.15,45.729) 12(57.15,48.269) 12(57.15,50.809) ""(39.37,30.489) ""(39.37,33.029)
  round 3.6 hole 2.7 paste-2.6: 666(2.35,2.359) 666(2.35,57.659) 666(57.65,2.359) 666(57.65,57.659)

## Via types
v1: diameter 0.55, hole 0.25, Top Layer to Bottom Layer, 102 vias
v2: diameter 0.55/0.55/0.8 (per signal layer), hole 0.25, Top Layer to Bottom Layer, tented top, 13 vias
v3: diameter 0.55, hole 0.25, Top Layer to Bottom Layer, tented top, 1 vias
v4: diameter 0.8, hole 0.4, Top Layer to Bottom Layer, 1 vias

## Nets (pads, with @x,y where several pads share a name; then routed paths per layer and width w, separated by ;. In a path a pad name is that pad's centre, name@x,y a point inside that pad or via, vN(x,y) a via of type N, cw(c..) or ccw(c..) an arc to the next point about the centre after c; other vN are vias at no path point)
CLK_OUT: R109.2 U100.32 | length 3.5
  Top Layer w0.175: R109.2@31.318,39.75 ccw(c30.875,40.191) 31.5,40.191 U100.32@31.5,43.184
D_N: R101.2 U100.3 | length 2.3
  Top Layer w0.15: U100.3@31,50.034 31,51.313 31.35,51.663 R101.2@31.35,52.159
D_P: R102.2 U100.4 | length 2.2
  Top Layer w0.15: R102.2@30.2,52.159 30.2,51.663 30.5,51.363 U100.4@30.5,50.034
EXT_CLK: pad.6@31.5,36.559 R109.1 U100.29 U200.7 | length 26.5
  Top Layer w0.175: v1(26.539,23.412) cw(c27.473,22.478) 27.473,23.799 U200.7@28.75,23.799 ; v3(29.85,41.509) ccw(c29.488,41.871) 30,41.871 U100.29@30,43.184 ; R109.1@31.3,38.509 31.3,37.939 ccw(c31.674,37.939) 31.409,37.675 cw(c31.191,37.456) 31.5,37.456 pad.6@31.5,36.559
  Bottom Layer w0.175: v1(26.539,23.412) 26.539,26.629 cw(c27.608,26.629) 26.852,27.385 27.144,27.677 ccw(c25.348,29.473) 27.888,29.473 27.888,31.894 cw(c30.428,31.894) 28.632,33.69 pad.6@31.5,36.559 31.5,38.807 ccw(c28.96,38.807) 30.756,40.603 v3(29.85,41.509)
GND: C101.1 C102.2 C103.1 C104.2 C105.1 C106.2 C107.1 C108.1 C110.1 C200.1 C201.1 C204.1 C205.1 C300.2 C301.2 C302.2 D200.1 J100.2@45.72,57.794 J100.10@50.8,57.794 J101.5 J102.1 J200.7@54.61,44.713 J202.6@6.35,30.489 J202.7@6.35,27.949 J204.6@29.16,4.949 J205.3@37.365,6.729 J205.5@37.365,5.459 J205.9@37.365,2.919 pad.0@3.81,27.949 pad.0@3.81,30.489 pad.2@8.89,5.089 pad.3@11.43,5.089 pad.4@13.97,5.089 pad.5@16.51,5.089 pad.6@41.91,5.089 pad.7@44.45,5.089 pad.8@46.99,5.089 pad.9@49.53,5.089 pad.10@52.07,5.089 pad.12@57.15,43.189 pad.666 Q102.2 R115.2 SW200.1 SW200.2 U100.5 U100.15 U100.23 U100.35 U100.43 U100.45 U200.23 U200.25 U300.2 XC100.2 XC100.4 | length 293.9
  Top Layer w0.175: v1(19.2,44.309) XC100.4@20.2,44.308 ; SW200.1@20.125,2.534 SW200.2@20.125,8.034 ; C204.1@20.3,10.309 SW200.2@20.3,8.456 ; XC100.2@21.8,46.508 v1(22.7,46.509) ; v1(22.86,45.321) 23.475,45.321 ; C106.2@23.475,44.784 C105.1@23.475,45.859 ; C104.2@24.775,47.609 U100.15@26.075,47.609 27.448,47.609 cw(c27.448,45.069) 29.244,46.865 U100.45@29.5,46.609 ; Q102.2@24.985,40.079 24.985,41.002 cw(c26.231,41.002) v1(25.35,41.884) C107.1@26.4,41.884 26.4,42.716 cw(c26.97,42.716) 26.567,43.119 cw(c26.724,42.961) 26.724,43.184 U100.23@27,43.184 27,44.46 cw(c27.175,44.46) U100.45@27.051,44.583 ; C103.1@28.95,53.309 v1(28.95,54.309) ; J204.6@29.15,4.925 cw(c29.184,4.925) J204.6@29.16,4.949 ; U100.5@30,50.034 v1(30,51.084) ; U100.45@31.25,44.634 ccw(c31.31,44.694) 31.31,44.609 U100.35@32.925,44.609 C102.2@34.25,44.609 ; v1(32.675,39.609) J102.1@32.675,40.484 ; U100.43@32.925,48.609 C101.1@34.225,48.609 ; C101.1@34.5,48.209 v1(35.25,48.209) ; SW200.2@20.125,8.034 ccw(c19.703,8.456) SW200.2@20.3,8.456 ; SW200.2@20.125,8.034 ccw(c19.703,8.456) SW200.2@20.3,8.456
  Top Layer w0.2: v1(28.8,28.413) 28.936,28.277 cw(c28.178,27.519) U200.23@29.25,27.519
  Top Layer w0.3: pad.0@3.81,27.949 J202.7@6.35,27.949 ; pad.0@3.81,30.489 J202.6@6.35,30.489 ; C108.1@23.4,49.809 23.55,49.659 v1(23.55,48.759) ; v1(23.54,26.55) C205.1@24.45,26.55 ; v1(23.557,27.861) C200.1@24.466,27.861 ; v1(23.557,29.111) C201.1@24.466,29.111 ; v1(25.315,66.72) R115.2@25.315,67.735 ; v1(26.458,66.747) C110.1@26.458,67.785 ; v4(26.747,61.689) C300.2@26.747,62.761 cw(c28.271,61.237) 28.271,63.392 U300.2@28.468,63.392 ; 28.7,68.809 J101.5@28.7,70.709 ; v1(29.02,60.802) C301.2@29.953,60.802 ; v1(32.586,67.064) C302.2@32.586,66.12 v1(33.911,66.12) ; J200.7@55.416,43.907 ccw(c57.15,45.641) pad.12@57.15,43.189
  Top Layer w0.5: v1@36.975,44.734 v1(37,44.734)
  Bottom Layer w0.175: 23.528,9.17 34.606,20.248 ; 23.528,10.969 25.672,8.825 ; 23.528,11.292 33.545,21.308 ; 23.528,13.09 27.793,8.825 ; 23.528,13.413 31.441,21.325 ; 23.528,15.212 29.915,8.825 ; 23.528,15.534 29.319,21.325 ; 23.528,17.333 32.036,8.825 ; 23.528,17.656 27.198,21.325 ; 23.528,19.454 34.157,8.825 ; 23.528,19.777 25.077,21.325 ; 23.528,21.308 33.545,21.308 ; 23.528,21.325 23.528,8.825 34.778,8.825 35.278,9.325 35.278,19.575 33.545,21.308 ; 23.779,21.325 35.278,9.826 ; 25.305,8.825 35.278,18.799 ; 25.9,21.325 35.278,11.947 ; 27.426,8.825 35.278,16.678 ; 28.021,21.325 35.278,14.068 ; 29.547,8.825 35.278,14.556 ; 30.143,21.325 35.278,16.19 ; 31.669,8.825 35.278,12.435 ; 32.264,21.325 35.278,18.311 ; 33.79,8.825 35.278,10.314
  Bottom Layer w0.3: v1@25.287,66.652 ccw(c25.219,66.72) v1(25.315,66.72)
  other v1: 20.125,5.284 29.3,24.959 30.7,24.959 29.3,26.359 30.7,26.359 28.4,44.409 30.6,44.409 27.3,45.509 29.5,45.509 31.7,45.509 28.4,46.609 30.6,46.609 27.3,47.709 29.5,47.709 31.7,47.709 28.4,48.809 30.6,48.809 29.43,66.447 27.52,68.053 28.181,68.757
  other v2: 29.65,67.339
NetC103_2: C103.2 U100.6 | length 2.3
  Top Layer w0.175: C103.2@28.95,52.209 28.95,51.816 ccw(c29.633,51.816) 29.15,51.334 cw(c28.305,50.489) 29.5,50.489 U100.6@29.5,50.034
NetC301_1: C301.1 U300.4 | length 2
  Top Layer w0.175: U300.4@30.585,62.439 U300.4@30.918,62.439 cw(c30.918,62.302) 31.055,62.302 31.053,62.299 C301.1@31.053,60.802
NetD100_1: D100.1 R114.1 | length 3.3
  Top Layer w0.175: v2(29.275,35.454) D100.1@29.275,36.759 29.275,37.241 cw(c31.067,37.241) R114.1@29.8,38.509
  Bottom Layer w0.175: v2@29.225,35.334 ccw(c29.104,35.454) v2(29.275,35.454)
NetD200_2: D200.2 R202.1 | length 1.4
  Top Layer w0.175: D200.2@33.067,1.517 ccw(c33.251,1.701) 33.243,1.441 ccw(c33.251,1.701) 33.251,1.441 R202.1@34.417,1.441
NetJ100_7: J100.7@49.53,56.524
NetJ100_8: J100.8@49.53,57.794
NetJ101_4: J101.4
NetJ102_2: J102.2 R118.1 U100.33 | length 5.6
  Top Layer w0.175: U100.33@32,43.184 32.323,43.184 cw(c32.323,40.644) R118.1@34.117,42.441 ; J102.2@32.675,41.834 cw(c33.58,40.928) 33.58,42.209 R118.1@34.35,42.209 ; R118.1@34.119,42.44 R118.1@34.35,42.209 ; v2(34.381,41.053) 34.381,42.133 ccw(c34.274,42.133) R118.1@34.35,42.209
NetJ103_1: J103.1 XC100.3 | length 2.5
  Top Layer w0.175: XC100.3@20.3,46.509 20.5,46.709 20.5,48.159 J103.1@20.75,48.409 ccw(c21.112,48.047) J103.1@20.6,48.047
NetJ200_1: J200.1@54.61,29.473 pad.12@57.15,27.949 | length 3.1
  Top Layer w0.3: J200.1@54.61,29.473 55.416,28.667 ccw(c57.15,30.401) pad.12@57.15,27.949
NetJ200_2: J200.2@54.61,32.013 pad.12@57.15,30.489 | length 3.1
  Top Layer w0.3: J200.2@54.61,32.013 55.416,31.207 ccw(c57.15,32.941) pad.12@57.15,30.489
NetJ202_1: J202.1@6.35,43.189 pad.0@3.81,43.189 | length 2.5
  Top Layer w0.3: pad.0@3.81,43.189 J202.1@6.35,43.189
NetJ205_6: J205.6@38.635,5.459
NetJ205_7: J205.7@37.365,4.189
NetJ205_8: J205.8@38.635,4.189
NetQ101_1: Q101.1 Q102.3 R105.1 | length 5.4
  Top Layer w0.175: R105.1@21.375,37.584 21.375,38.543 cw(c22.059,38.543) 21.575,39.026 cw(c21.822,38.779) 21.822,39.129 Q102.3@22.885,39.129 22.885,37.559 Q101.1@22.885,36.579
NetQT200_1: R203.1 | length 7.3
  Top Layer w0.175: v1(23.45,23.309) 24.376,23.309 ccw(c24.376,23.365) R203.1@24.416,23.325
  GND w0.175: v1(23.45,23.309) 23.45,21.404 ccw(c25.99,21.404) 24.194,19.608 24.494,19.308 ccw(c25.836,20.65) 25.836,18.752 26.322,18.752
NetU100_8: U100.8 | length 2.4
  Top Layer w0.175: v2(27.648,52.175) 27.648,51.986 27.65,51.984 ccw(c28.616,51.984) 27.933,51.301 28.375,50.859 cw(c28.073,50.557) 28.5,50.557 U100.8@28.5,50.034
NetU100_11: U100.11
NetU100_12: U100.12 | length 0.6
  Top Layer w0.175: U100.12@26.075,49.109 v2(26.075,49.648)
  Bottom Layer w0.175: v2@26.05,49.709 cw(c25.99,49.648) v2(26.075,49.648)
NetU100_18: U100.18 | length 2.4
  Top Layer w0.175: v2@24.9,46.109 24.926,46.082 v2(24.926,46.036) ; v2(24.926,46.036) cw(c25.102,45.86) v2@25.102,46.109 ; v2(24.926,46.036) cw(c25.102,45.86) v2@25.102,46.109 ; v2@25.102,46.109 U100.18@26.075,46.109 v2@25.102,46.109
NetU100_19: U100.19 | length 3.9
  Top Layer w0.175: v2(23.975,42.884) ccw(c22.703,44.156) 24.502,44.156 cw(c26.203,44.156) 25,45.359 cw(c25.603,44.756) 25.603,45.609 U100.19@26.075,45.609
NetU100_22: U100.22 | length 1
  Top Layer w0.175: v2(25.85,43.134) 25.9,43.184 ccw(c25.478,43.606) 26.075,43.606 U100.22@26.075,44.109
NetU100_26: U100.26
NetU100_27: U100.27
NetU100_40: U100.40
NetU100_41: U100.41
PA02: J203.1@6.35,20.329 pad.0@3.81,20.329 U200.1 | length 27.8
  Top Layer w0.175: J203.1@6.35,20.329 6.879,20.858 cw(c8.45,19.288) 8.45,21.509 17.745,21.509 ccw(c17.745,22.709) 18.593,21.86 ccw(c18.157,22.297) 18.774,22.297 18.774,22.513 cw(c21.314,22.513) 19.518,24.309 21.69,26.481 cw(c23.486,24.684) 23.486,27.224 27.378,27.224 cw(c27.378,26.146) U200.1@28.14,26.909
  Top Layer w0.3: pad.0@3.81,20.329 J203.1@6.35,20.329
PA03: C205.2 J200.8@54.61,47.253 J203.2@6.35,17.789 pad.0@3.81,17.789 pad.12@57.15,45.729 U200.2 | length 74
  Top Layer w0.175: J203.2@6.35,17.789 6.854,18.293 cw(c8.65,16.497) 8.65,19.037 17.061,19.037 ccw(c17.061,21.577) 18.857,19.781 ccw(c18.256,20.381) 19.106,20.381 19.106,22.645 ; 19.099,22.499 cw(c20.762,22.499) 19.106,22.645 ; C205.2@25.692,26.609 ccw(c25.692,26.408) C205.2@25.55,26.55 25.55,26.179 cw(c25.144,26.179) 25.548,26.138 cw(c25.144,26.179) 25.431,25.893 cw(c25.235,26.089) 25.235,25.811 22.515,25.811 ccw(c22.515,23.897) 21.162,25.251 19.586,23.675 ccw(c20.762,22.499) 19.106,22.645 ; v1(35.489,35.112) 39.395,39.018 ccw(c37.599,40.814) 40.139,40.814 40.139,45.033 cw(c41.825,45.033) 40.632,46.226 cw(c42.429,44.43) 42.429,46.97 52.425,46.97 ccw(c52.425,47.312) 52.667,47.07 cw(c53.109,46.629) 53.109,47.253 J200.8@54.61,47.253
  Top Layer w0.22: C205.2@25.692,26.609 v1(27.1,26.609) ; v1@27.139,26.654 ccw(c27.732,27.247) 27.732,26.409 U200.2@28.14,26.409
  Top Layer w0.3: pad.0@3.81,17.789 J203.2@6.35,17.789 ; J200.8@54.61,47.253 55.416,46.447 ccw(c57.15,48.181) pad.12@57.15,45.729
  Bottom Layer w0.175: v1(27.1,26.609) 27.578,27.087 ccw(c26,28.665) 28.232,28.665 28.232,30.613 cw(c30.022,30.613) 28.756,31.879 31.245,34.368 cw(c33.041,32.572) 33.041,35.112 v1(35.489,35.112)
PA04: J203.3@6.35,15.249 pad.0@3.81,15.249 U200.3 | length 31.3
  Top Layer w0.175: J203.3@6.35,15.249 J203.3@6.883,15.781 ; J203.3@6.883,15.782 cw(c8.441,14.223) 8.441,16.427 17.197,16.427 ccw(c17.197,18.967) 18.993,17.171 ccw(c17.906,18.258) 19.382,17.83 ccw(c17.906,18.258) 19.443,18.258 19.443,21.844 cw(c21.983,21.844) 20.187,23.64 20.949,24.402 cw(c22.55,22.802) 20.95,24.403 21.286,24.739 cw(c23.082,22.943) 23.082,25.483 25.561,25.483 ccw(c25.561,26.2) 25.591,25.484 ccw(c25.561,26.2) 25.946,25.595 cw(c26.702,24.839) 26.702,25.909 U200.3@28.14,25.909
  Top Layer w0.3: pad.0@3.81,15.249 J203.3@6.35,15.249
PA05: J203.4@6.35,12.709 pad.0@3.81,12.709 U200.4 | length 33
  Top Layer w0.175: J203.4@6.35,12.709 6.84,13.199 cw(c8.636,11.403) 8.636,13.943 17.006,13.943 ccw(c17.006,16.483) 18.802,14.687 19.049,14.934 ccw(c17.253,16.73) 19.793,16.73 19.793,21.467 cw(c22.333,21.467) 20.537,23.263 21.578,24.304 cw(c23.374,22.508) 23.374,25.048 25.492,25.048 ccw(c25.492,25.908) 26.1,25.3 cw(c26.362,25.038) 26.362,25.409 U200.4@28.14,25.409
  Top Layer w0.3: pad.0@3.81,12.709 J203.4@6.35,12.709
PA06: J203.5@6.35,10.169 pad.0@3.81,10.169 U200.5 | length 35.3
  Top Layer w0.175: J203.5@6.35,10.169 6.916,10.734 cw(c8.712,8.938) 8.712,11.478 17.922,11.478 ccw(c17.922,13.568) 19.399,12.09 ccw(c17.603,13.886) 20.143,13.886 20.143,21.037 cw(c22.683,21.037) 20.887,22.833 21.909,23.855 cw(c23.706,22.059) 23.706,24.599 25.6,24.599 ccw(c25.6,25.257) 26.065,24.792 cw(c26.347,24.51) 26.347,24.909 U200.5@28.14,24.909
  Top Layer w0.3: pad.0@3.81,10.169 J203.5@6.35,10.169
PA07: J203.6@6.35,7.629 pad.0@3.81,7.629 R203.2 U200.6 | length 35.9
  Top Layer w0.175: J203.6@6.35,7.629 6.827,8.105 cw(c8.623,6.309) 8.623,8.849 15.986,8.849 ccw(c15.986,11.389) 17.782,9.593 19.749,11.56 ccw(c17.953,13.356) 20.493,13.356 20.493,20.286 cw(c23.033,20.286) 21.237,22.082 cw(c22.02,21.3) 22.02,22.407 23.158,22.407 23.645,22.407 ccw(c23.645,24.947) 25.441,23.151 R203.2@25.616,23.325 25.955,23.665 cw(c27.752,21.869) 27.752,24.409 U200.6@28.14,24.409
  Top Layer w0.3: pad.0@3.81,7.629 J203.6@6.35,7.629
PA09: J200.6@54.61,42.173 J204.3@31.7,7.489 pad.10@52.07,30.489 pad.12@57.15,40.649 R202.2 U200.8 | length 89.6
  Top Layer w0.175: U200.8@29.25,23.799 29.25,22.988 ccw(c31.256,22.988) 29.838,21.57 ccw(c30.251,21.984) 30.251,21.398 36.174,21.398 cw(c36.174,19.271) v1(37.678,20.775) ccw(c37.711,20.743) 37.665,20.743 37.665,18.701 cw(c36.466,18.701) 37.314,17.853 ccw(c37.925,17.242) 37.061,17.242 37.061,13.516 cw(c34.556,13.936) 36.352,12.14 J204.3@31.7,7.489 31.236,7.025 ccw(c33.032,5.229) 30.492,5.229 30.492,4.36 ccw(c31.274,4.36) 30.721,3.807 ccw(c31.829,4.915) 31.829,3.349 33.461,3.349 cw(c33.461,2.569) 34.012,3.12 34.364,2.769 cw(c34.236,2.641) R202.2@34.417,2.641
  Top Layer w0.3: J200.6@55.416,41.367 ccw(c57.15,43.101) pad.12@57.15,40.649
  Bottom Layer w0.175: v1(37.678,20.775) cw(c37.708,20.805) 37.666,20.805 37.666,28.051 ; pad.10@52.07,30.489 51.613,30.031 cw(c49.816,31.827) 49.816,29.287 41.304,29.287 ccw(c41.304,27.358) 39.94,28.722 cw(c39.094,29.568) 39.284,28.387 cw(c39.094,29.568) 39.094,28.372 38,28.372 ; J200.6@54.61,42.173 53.21,42.173 ccw(c53.21,41.751) 52.912,42.049 cw(c52.695,42.266) 52.695,41.959 39.255,41.959 ccw(c39.255,40.418) 38.165,41.508 ccw(c39.371,40.302) 37.666,40.302 37.666,28.648 ; 37.666,28.051 37.666,28.372 ; 37.666,28.051 38,28.372 ; 37.666,28.372 38,28.372 ; 37.666,28.372 37.666,28.648 ; 37.666,28.648 38,28.372
PA10: J201.2@54.61,10.169 pad.12@57.15,10.169 R108.2 U200.9 | length 62.6
  Top Layer w0.175: v1(19.625,38.865) R108.2@19.625,39.959 ; U200.9@29.75,23.799 29.75,23.019 ccw(c31.286,23.019) v1(30.2,21.932) 36.364,21.932 36.626,21.933 cw(c36.626,20.052) 37.956,21.382 cw(c36.183,19.608) 38.691,19.608 38.691,14.456 cw(c37.234,14.456) v1(38.264,13.426) ; v1@40.072,12.672 40.64,12.104 ccw(c42.436,13.9) 42.436,11.36 52.367,11.36 cw(c52.367,8.82) 54.163,10.616 J201.2@54.61,10.169
  Top Layer w0.3: J201.2@54.61,10.169 pad.12@57.15,10.169
  Bottom Layer w0.175: v1(19.625,38.865) cw(c18.004,37.244) 20.296,37.244 20.296,28.856 ccw(c22.836,28.856) 21.04,27.06 25.547,22.553 ccw(c27.045,24.05) 27.045,21.932 v1(30.2,21.932) ; v1(38.264,13.426) 38.369,13.426 cw(c38.369,10.969) v1(40.106,12.707)
PA11: J201.1@54.61,7.629 pad.12@57.15,7.629 R107.2 U200.10 | length 64.6
  Top Layer w0.175: v1(20.875,39.804) R107.2@20.875,40.709 ; U200.10@30.25,23.799 30.25,23.226 ccw(c31.02,23.226) 30.476,22.682 ccw(c31.028,23.234) 31.028,22.453 36.555,22.453 cw(c36.555,20.008) 38.284,21.737 cw(c36.488,19.941) 39.028,19.941 39.028,11.897 ccw(c41.568,11.897) 39.772,10.1 40.044,9.828 ccw(c41.84,11.624) 41.84,9.084 52.102,9.084 cw(c52.102,6.544) 53.898,8.34 J201.1@54.61,7.629
  Top Layer w0.3: J201.1@54.61,7.629 pad.12@57.15,7.629
  Bottom Layer w0.175: v1(20.875,39.804) 20.875,28.869 ccw(c23.415,28.869) 21.619,27.073 25.473,23.219 ; 25.473,23.219 ccw(c27.269,25.015) 27.269,22.475 v1(31.178,22.475)
PA14: J200.9@54.61,49.793 pad.12@57.15,48.269 U200.11 | length 50.9
  Top Layer w0.175: U200.11@30.75,23.799 30.75,23.47 ccw(c31.15,23.47) 31.15,23.07 35.37,23.07 ccw(c35.37,24.564) v1(36.426,23.507)
  Top Layer w0.3: J200.9@54.61,49.793 55.416,48.987 ccw(c57.15,50.721) pad.12@57.15,48.269
  Bottom Layer w0.175: v1(36.426,23.507) 36.5,23.581 ccw(c34.704,25.377) 37.244,25.377 37.244,40.606 cw(c39.784,40.606) 37.988,42.402 38.18,42.594 ccw(c36.384,44.39) 38.924,44.39 38.924,47.732 cw(c39.906,47.732) 39.211,48.426 39.573,48.788 cw(c41.369,46.992) 41.369,49.532 52.482,49.532 ccw(c52.482,49.648) 52.565,49.566 cw(c53.112,49.018) 53.112,49.793 J200.9@54.61,49.793
PA15: J200.10@54.61,52.333 pad.12@57.15,50.809 U200.12 | length 51.9
  Top Layer w0.175: U200.12@31.25,23.799 v1(35.408,23.799)
  Top Layer w0.3: J200.10@54.61,52.333 55.416,51.527 ccw(c57.15,53.261) pad.12@57.15,50.809
  Bottom Layer w0.175: v1(35.408,23.799) 36.175,24.565 ccw(c34.379,26.361) 36.919,26.361 36.919,41.02 cw(c39.459,41.02) 37.663,42.816 37.974,43.126 ccw(c36.464,44.636) 38.599,44.636 38.599,50.328 cw(c40.382,50.328) 39.121,51.589 cw(c40.917,49.793) 40.917,52.333 J200.10@54.61,52.333
PA16: J201.3@54.61,12.709 pad.12@57.15,12.709 U200.13 | length 33.2
  Top Layer w0.175: U200.13@31.86,24.409 35.364,24.409 cw(c35.364,21.869) 37.16,23.665 38.622,22.203 cw(c36.826,20.407) 39.366,20.407 39.366,16.055 ccw(c41.222,16.055) 39.91,14.742 ccw(c41.706,16.538) 41.706,13.998 52.268,13.998 cw(c52.268,11.458) 54.064,13.254 J201.3@54.61,12.709
  Top Layer w0.3: J201.3@54.61,12.709 pad.12@57.15,12.709
PA17: J201.4@54.61,15.249 pad.12@57.15,15.249 U200.14 | length 30.9
  Top Layer w0.175: U200.14@31.86,24.909 35.581,24.909 cw(c35.581,22.369) 37.377,24.165 38.995,22.547 cw(c37.199,20.751) 39.739,20.751 39.739,19.162 ccw(c42.279,19.162) 40.483,17.366 40.634,17.215 ccw(c42.43,19.011) 42.43,16.471 52.336,16.471 cw(c52.336,13.931) 54.132,15.727 J201.4@54.61,15.249
  Top Layer w0.3: J201.4@54.61,15.249 pad.12@57.15,15.249
PA22: J200.4@54.61,37.093 J204.4@31.7,4.949 pad.10@52.07,33.029 pad.12@57.15,35.569 U200.15 | length 63.9
  Top Layer w0.175: J204.4@31.7,4.949 32.044,5.292 cw(c33.84,3.496) 33.84,6.036 34.744,6.036 ccw(c34.744,7.042) 35.456,6.331 ccw(c34.82,6.966) 35.719,6.966 35.719,9.248 cw(c38.259,9.248) 36.463,11.044 36.642,11.223 ccw(c34.846,13.019) 37.386,13.019 37.386,15.483 cw(c39.926,15.483) 38.13,17.279 v1(38.16,17.309) ; U200.15@31.86,25.409 32.837,25.409 ccw(c32.837,27.162) v1(34.076,25.922) ccw(c33.324,26.674) 34.388,26.674 34.388,31.745 cw(c36.411,31.745) 34.98,33.175 35.63,33.825 cw(c37.426,32.029) 37.426,34.569 49.477,34.569 cw(c49.477,32.029) 51.273,33.825 pad.10@52.07,33.029
  Top Layer w0.3: J200.4@55.416,36.287 ccw(c57.15,38.021) pad.12@57.15,35.569
  Bottom Layer w0.175: J204.4@31.515,5.394 cw(c31.07,4.949) J204.4@31.7,4.949 ; v1(34.076,25.922) 34.076,24.574 ccw(c36.616,24.574) 34.82,22.778 37.416,20.183 cw(c35.62,18.387) 38.16,18.387 v1(38.16,17.309) ; pad.10@52.07,33.029 51.469,33.63 cw(c53.265,35.426) 50.725,35.426 50.725,35.467 cw(c51.971,35.467) 51.09,36.349 cw(c52.886,34.553) 52.886,37.093 J200.4@54.61,37.093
